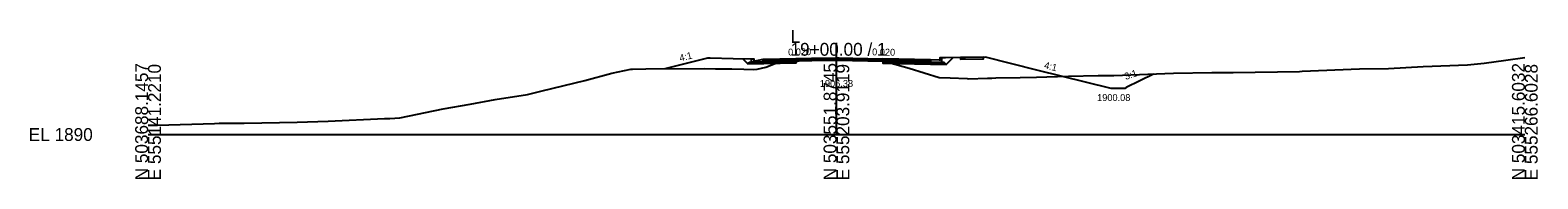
# Model space of a CAD drawing. Extents: x -26 to 4603, y -10 to 4703.
# Drawn here: x -25.7 to 302.8, y 3975.3 to 4007.8 of the extents above; entities that cross this region are included whole.
import ezdxf

# ---------------------------------------------------------------- set-up
doc = ezdxf.new("R2010")
doc.units = 0
for name, color, linetype in [('Default', 7, 'Continuous'), ('Exist Cross Section Cell', 7, 'Continuous'), ('Exist XS Ground Line', 7, 'Continuous'), ('Prop CMT Pvmt Course 1', 7, 'Continuous'), ('Prop CMT Pvmt Course 2', 7, 'Continuous'), ('Prop CMT Pvmt Course 3', 7, 'Continuous'), ('Prop CMT Pvmt Milling', 7, 'Continuous'), ('Prop CMT Shear Line', 7, 'Continuous'), ('Prop CMT Shld Paved Course 2', 7, 'Continuous'), ('Prop CMT Shld Paved Course 3', 7, 'Continuous'), ('Prop CMT Subgrade Earthwork', 7, 'Continuous'), ('Prop Conc 4in Sidewalk', 7, 'Continuous'), ('Prop Conc Curb and Gutter', 7, 'Continuous'), ('Prop XS Ditch Slope Text', 7, 'Continuous'), ('Prop XS Finish Grade', 7, 'Continuous'), ('Prop XS Label Text', 7, 'Continuous'), ('Prop XS SS Elevation Text', 7, 'Continuous'), ('Scratch_Level_9', 7, 'Continuous')]:
    doc.layers.add(name, color=color, linetype=linetype)

msp = doc.modelspace()

# ---------------------------------------------------------------- linework, layer by layer
at = {"layer": 'Exist Cross Section Cell'}
for p, q in [((150, 3985), (150, 4005)), ((0, 3985), (150, 3985)), ((150, 3985), (300, 3985))]:
    msp.add_line(p, q, dxfattribs=at)
at = {"layer": 'Exist XS Ground Line'}
msp.add_lwpolyline([(0, 3987.07), (2.07, 3987.07), (14.45, 3987.43), (15.52, 3987.45), (16.02, 3987.5), (16.2, 3987.51), (20.92, 3987.45), (32.46, 3987.71), (39.28, 3987.95), (51.52, 3988.48), (52.65, 3988.52), (54.89, 3988.65), (64.34, 3990.58), (70.21, 3991.62), (75.64, 3992.68), (82.66, 3993.76), (85.89, 3994.54), (95.17, 3996.76), (101.05, 3998.42), (105.19, 3999.26), (105.57, 3999.28), (108.44, 3999.37), (121.15, 3999.45), (123.64, 3999.37), (123.76, 3999.35), (124.18, 3999.35), (124.46, 3999.36), (127.18, 3999.32), (129.82, 3999.25), (131.94, 3999.22), (132.71, 3999.25), (134.64, 3999.68), (136.99, 4000.67), (139.58, 4000.95), (140.06, 4001.06), (141.22, 4001.2), (141.38, 4001.21), (141.91, 4001.31), (144.63, 4001.35), (150.59, 4001.38), (153.6, 4001.3), (160.11, 4001.12), (165.87, 3999.48), (172.4, 3997.45), (174.8, 3997.38), (178.48, 3997.24), (178.79, 3997.16), (182.95, 3997.31), (183.86, 3997.3), (184.7, 3997.35), (190.07, 3997.45), (193.62, 3997.54), (195.87, 3997.58), (200.59, 3997.72), (207.04, 3997.86), (210.43, 3997.9), (223.46, 3998.36), (231.77, 3998.52), (236.47, 3998.53), (250.89, 3998.79), (251.46, 3998.81), (263.98, 3999.34), (270.32, 3999.44), (277.85, 3999.82), (287.49, 4000.18), (291.11, 4000.61), (295.84, 4001.22), (300, 4001.78)], dxfattribs=at)
at = {"layer": 'Prop CMT Pvmt Course 1'}
for points in [[(134, 4001.43), (141.22, 4001.57), (141.22, 4001.32), (141.22, 4001.32), (134, 4001.18), (134, 4001.18), (134, 4001.18), (134, 4001.43), (134, 4001.43)], [(150, 4001.75), (150, 4001.75), (150, 4001.38), (150, 4001.38), (150, 4001.38), (144.63, 4001.35), (144.63, 4001.35), (141.91, 4001.31), (141.38, 4001.21), (141.38, 4001.21), (141.22, 4001.2), (141.22, 4001.2), (141.22, 4001.57), (141.38, 4001.58), (141.38, 4001.58), (141.91, 4001.59), (144.63, 4001.64), (144.63, 4001.64), (150, 4001.75)], [(160.11, 4001.55), (160.11, 4001.12), (160.11, 4001.12), (160.11, 4001.12), (153.6, 4001.3), (153.6, 4001.3), (150.59, 4001.38), (150.59, 4001.38), (150, 4001.38), (150, 4001.38), (150, 4001.75), (150.59, 4001.74), (150.59, 4001.74), (153.6, 4001.68), (153.6, 4001.68), (160.11, 4001.55), (160.11, 4001.55)], [(170.5, 4001.34), (160.11, 4001.55), (160.11, 4001.3), (160.11, 4001.3), (170.5, 4001.09), (170.5, 4001.09), (170.5, 4001.09), (170.5, 4001.34), (170.5, 4001.34)]]:
    msp.add_lwpolyline(points, dxfattribs=at)
at = {"layer": 'Prop CMT Pvmt Course 2'}
for points in [[(134, 4001.18), (141.22, 4001.32), (141.22, 4000.99), (141.22, 4000.99), (134, 4000.85), (134, 4000.85), (134, 4000.85), (134, 4001.18), (134, 4001.18)], [(170.5, 4001.09), (160.11, 4001.3), (160.11, 4000.96), (160.11, 4000.96), (170.5, 4000.76), (170.5, 4000.76), (170.5, 4000.76), (170.5, 4001.09), (170.5, 4001.09)]]:
    msp.add_lwpolyline(points, dxfattribs=at)
at = {"layer": 'Prop CMT Pvmt Course 3'}
for points in [[(134, 4000.85), (141.22, 4000.99), (141.22, 4000.62), (141.22, 4000.62), (134, 4000.47), (134, 4000.47), (134, 4000.47), (134, 4000.85), (134, 4000.85)], [(170.5, 4000.76), (160.11, 4000.96), (160.11, 4000.59), (160.11, 4000.59), (170.5, 4000.38), (170.5, 4000.38), (170.5, 4000.38), (170.5, 4000.76), (170.5, 4000.76)], [(170.5, 4000.76), (170.5, 4000.38), (170.5, 4000.38), (173.89, 4000.31), (173.5, 4000.69), (170.5, 4000.76), (170.5, 4000.76)]]:
    msp.add_lwpolyline(points, dxfattribs=at)
at = {"layer": 'Prop CMT Pvmt Milling'}
for points in [[(141.22, 4001.2), (141.38, 4001.21), (141.38, 4001.21), (141.91, 4001.31), (144.63, 4001.35), (144.63, 4001.35), (150, 4001.38), (150, 4001.38)], [(160.11, 4001.12), (160.11, 4001.12), (153.6, 4001.3), (153.6, 4001.3), (150.59, 4001.38), (150.59, 4001.38), (150, 4001.38)]]:
    msp.add_lwpolyline(points, dxfattribs=at)
at = {"layer": 'Prop CMT Shld Paved Course 2'}
for points in [[(150, 4001.5), (150, 4001.5), (150, 4001.17), (150, 4001.17), (150, 4001.17), (144.63, 4001.06), (144.63, 4001.06), (141.91, 4001), (141.38, 4000.99), (141.38, 4000.99), (141.22, 4000.99), (141.22, 4000.99), (141.22, 4001.32), (141.38, 4001.33), (141.38, 4001.33), (141.91, 4001.34), (144.63, 4001.39), (144.63, 4001.39), (150, 4001.5)], [(160.11, 4001.3), (160.11, 4000.96), (160.11, 4000.96), (160.11, 4000.96), (153.6, 4001.09), (153.6, 4001.09), (150.59, 4001.16), (150.59, 4001.16), (150, 4001.17), (150, 4001.17), (150, 4001.5), (150.59, 4001.49), (150.59, 4001.49), (153.6, 4001.43), (153.6, 4001.43), (160.11, 4001.3), (160.11, 4001.3)]]:
    msp.add_lwpolyline(points, dxfattribs=at)
at = {"layer": 'Prop CMT Shld Paved Course 3'}
msp.add_lwpolyline([(131, 4000.79), (134, 4000.85), (134, 4000.47), (134, 4000.47), (130.7, 4000.41), (130.7, 4000.41), (130.7, 4000.41), (131, 4000.79), (131, 4000.79)], dxfattribs=at)
at = {"layer": 'Prop CMT Subgrade Earthwork'}
for points in [[(129.54, 4001.57), (130.7, 4000.41), (130.7, 4000.41)], [(170.5, 4000.38), (170.5, 4000.38), (173.89, 4000.31), (175.34, 4001.76)], [(130.7, 4000.41), (130.7, 4000.41), (141.22, 4000.62)], [(173.89, 4000.31), (173.89, 4000.31), (160.11, 4000.59)]]:
    msp.add_lwpolyline(points, dxfattribs=at)
at = {"layer": 'Prop Conc 4in Sidewalk'}
msp.add_lwpolyline([(177.01, 4001.79), (177.01, 4001.46), (182.01, 4001.56), (182.01, 4001.89), (177.01, 4001.79)], dxfattribs=at)
at = {"layer": 'Prop Conc Curb and Gutter'}
for points in [[(132, 4001.03), (134, 4001.43), (134, 4000.85), (134, 4000.85), (131.5, 4000.8), (131.5, 4000.8), (131.5, 4000.8), (131.5, 4001.53), (132, 4001.53), (132, 4001.53), (132, 4001.03), (132, 4001.03), (132, 4001.03)], [(170.5, 4001.34), (170.5, 4001.34), (170.5, 4001.34), (170.5, 4000.76), (170.5, 4000.76), (170.5, 4000.76), (172.85, 4000.71), (173, 4000.7), (173, 4000.77), (173, 4001.72), (172.53, 4001.72), (172.5, 4001.72), (172.5, 4001.24), (172.5, 4001.22), (172.41, 4001.22), (170.5, 4001.34), (170.5, 4001.34)]]:
    msp.add_lwpolyline(points, dxfattribs=at)
at = {"layer": 'Prop XS Finish Grade'}
msp.add_line((122.5, 4001.71), (127.5, 4001.61), dxfattribs=at)
for points in [[(112.7, 3999.4), (122, 4001.72), (122, 4001.72)], [(122, 4001.72), (122.5, 4001.71), (122.5, 4001.71)], [(127.5, 4001.61), (131.5, 4001.53), (131.5, 4001.53)], [(209.84, 3995.08), (193.69, 3999.08), (182.51, 4001.9), (173.8, 4001.73), (173, 4001.72)], [(219.06, 3998.21), (213.14, 3995.24), (212.83, 3995.08), (209.84, 3995.08), (209.84, 3995.08), (209.84, 3995.08)]]:
    msp.add_lwpolyline(points, dxfattribs=at)
at = {"layer": 'Scratch_Level_9'}
msp.add_lwpolyline([(134, 4001.43), (134, 4001.18)], dxfattribs=at)

# ---------------------------------------------------------------- texts
at = {"layer": 'Default'}
msp.add_text('-', height=0.0001, dxfattribs=at).set_placement((0, 3985))
at = {"layer": 'Exist Cross Section Cell'}
for s, p in [('19+00.00 / 1', (140, 4002.2)), ('L', (140, 4005)), ('EL 1890', (-26, 3983.6))]:
    msp.add_text(s, height=2.8, dxfattribs=at).set_placement(p)
for s, p in [('N 503688.1457', (0, 3975)), ('E 555141.2210', (2.8, 3975)), ('N 503551.8745', (150, 3975)), ('E 555203.9119', (152.8, 3975)), ('N 503415.6032', (300, 3975)), ('E 555266.6028', (302.8, 3975))]:
    msp.add_text(s, height=2.8, rotation=90, dxfattribs=at).set_placement(p)
at = {"layer": 'Prop CMT Shear Line'}
for p in [(122, 4001.72), (122.5, 4001.71), (127.5, 4001.61), (150, 4001.75), (177, 4001.79), (182.01, 4001.89), (182.51, 4001.9), (112.7, 3999.39), (132, 4001.03), (134, 4001.43), (134, 4001.43), (170.5, 4001.34), (172.5, 4001.22), (209.84, 3995.08), (219.05, 3998.21)]:
    msp.add_text('X', height=0.0025, dxfattribs=at).set_placement(p)
at = {"layer": 'Prop XS Ditch Slope Text'}
msp.add_text('1900.08', height=1.5, dxfattribs=at).set_placement((206.8, 3992.31))
at = {"layer": 'Prop XS Label Text'}
for s, rotation, p in [('4:1', 14.0362, (115.98, 4000.94)), ('0.020', 1.1458, (139.48, 4002.24)), ('0.020', 358.8542, (157.76, 4002.3)), ('4:1', 345.9903, (195.15, 3999.47)), ('3:1', 18.741, (213.05, 3996.91))]:
    msp.add_text(s, height=1.5, rotation=rotation, dxfattribs=at).set_placement(p)
at = {"layer": 'Prop XS SS Elevation Text'}
msp.add_text('1906.38', height=1.5, dxfattribs=at).set_placement((146.38, 3995.4))

doc.saveas('drawing.dxf')
